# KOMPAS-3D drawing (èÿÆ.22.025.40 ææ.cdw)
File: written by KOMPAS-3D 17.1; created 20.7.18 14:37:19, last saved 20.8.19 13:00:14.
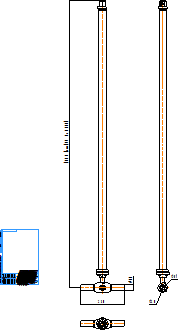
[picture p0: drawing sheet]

Sheet 1: A4, portrait

Title block, sheet 1: name: КШТ.22.025.40 С/С; sheets: 1; sheet format: A4; stored path: C:\Users\kka\KOMPAS_Work\Модели кранов для исследований\DN32\С удлинением\КШТ.22.032.40 СС.cdw

Referenced files in C:\Users\kka\KOMPAS_Work\Модели кранов для исследований\DN25\: АПТА.0203-1215.04.01 _ Корпус крана Ду25.m3d, АПТА.0203-1215.02.01 _ Патрубок сварной точенный Ду25 (труба по ГОСТ).m3d, АПТА.0203-2609.00.01 _ Шар Ду25.m3d, АПТА.0203-2609.02.03 _ Пружина тарельчатая Ду25.m3d, АПТА.0203-2609.02.04 _ Кольцо опорное Ду25.m3d, АПТА.0203-2609.02.05 _ Уплотнение седловое Ду25.m3d, АПТА.0203-2609.04.02 _ Шток Ду25 исполнение 1.m3d, АПТА.0203-1018.04.02 _ Корпус штока Ду10-32.m3d, АПТА.0203-1018.04.04 _ Шайба фрикционная Ду10-32.m3d, АПТА.0203-2609.02.02 _ Кольцо горловое Ду25.m3d, АПТА.0203-1215.00.00 _ Кран шаровой сварной Ду25 (Труба по ГОСТ).a3d!АПТА.0203-1215.00.00!Деталь (локальная).m3d, АПТА.0203-1215.00.00 _ Кран шаровой сварной Ду25 (Труба по ГОСТ).a3d!АПТА.0203-1215.00.00!Деталь (локальная) 1.m3d, Кольцо EPDM 10.3x2.4.m3d, АПТА.0203-1018.01.01 _ Кольцо прокладочное Ду10-32.m3d, Кольцо Viton 10.3x2.4.m3d, АПТА.0203-1018.01.02 _ Подкладка для кольца Ду10-32.m3d, АПТА.0203-1215.00.00 _ Кран шаровой сварной Ду25 (Труба по ГОСТ).a3d
Referenced files in C:\Program Files\ASCON\KOMPAS-3D v17\Libs\PartLib\DATA\VAULT\methods\kompas\3d\: PLib_Pin_3128_712.m3d, PLib_Blind_Nut_type1_900.m3d, PLib_Bolt_1_900.m3d, PLib_Washer_2_712.m3d, PLib_Pins_GOST_14229_911.m3d, PLib_Screw_GOST_8878-84_900.m3d
Referenced files in C:\Users\kka\KOMPAS_Work\Модели кранов для исследований\DN32\: ручка15-32.m3d, АПТА.0203-1018.03.00 _ Ручка Ду10-32.a3d
Referenced files in C:\Users\kka\KOMPAS_Work\КШ удлиненные ПП МОСФЛОУЛАЙН ф. ADL\DN25ПП\: ухватка15-32.m3d
Referenced files in C:\Users\kka\KOMPAS_Work\Удлинения БИВАЛ ф. ADL\Небюджет\Удлинения_2010\УШДн15-32\: УШ.251.00.03 _ Фланец нижний.m3d, УШ.251.00.07 _ Прокладка Ду20-50.m3d, УШ.251.00.05 _ Шток удлинителя Ду20-50.m3d, УШ.251.00.04 _ Гайка 32.m3d, УШ.251.00.01 _ Крышка удлинения.m3d, УШ.251.00.06 _ Тело удлинителя Ду20-50.m3d, УШ.251.00.08 _ Адаптер Ду20-32.m3d, УШ.251.00.00 _ Удлинение штока Ду20-32.a3d!УШ.251.00.00!Деталь (локальная).m3d, АПТА.0203-2617.11.03 - Кольцо прокладочное Ду65-80.m3d, УШ.251.00.00 _ Удлинение штока Ду20-32.a3d!УШ.251.00.00!Деталь (локальная) 1.m3d, УШ.251.00.00 _ Удлинение штока Ду20-32.a3d
Referenced files in C:\Users\kka\KOMPAS_Work\Удлинения БИВАЛ ф. ADL\Небюджет\Специальные ISO фланцы\: Фланец Ду15-32.m3d
Referenced files in C:\Users\kka\KOMPAS_Work\Модели кранов для исследований\DN80\: Кольцо EPDM 19.2x3.m3d
Referenced files in C:\Users\kka\KOMPAS_Work\Модели кранов для исследований\DN25\С удлинением\: КШТ.22.025.40 СС.a3d
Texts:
  kka
  adl
  Рама для чертежей
  Лит-Масса-Масштаб
  Материал-Предприятие
  Масштаб
  Изм.
  Лист
  № докум.
  Подп.
  Дата
  Лит.
  Разраб.
  Пров.
  Т.контр.
  Листов
  Внимание! Данный продукт является объектом авторского права ООО «Торговый Дом АДЛ».
  Запрещается изменение, копирование, распространение
  (в том числе путем копирования на другие сайты и ресурсы в Интернете)
  или любое иное использование информации и объектов без предварительного
  согласия правообладателя (ООО «Торговый Дом АДЛ»).
  Н.контр.
  Утв.
  ООО "Торговый дом АДЛ"
  Изменение
  Номер документа
  Подпись
  Обозначение документа
  Наименование изделия
  Масса изделия по ГОСТ 2.109-73
  Порядковый номер листа
  Общее количество листов в документе
  Характер работы, выполненной лицом, подписавшим документ
  Наименование или индекс предприятия, выпускающего документ
  Инв. № подл.
  Подп. и дата
  Взам. инв. №
  Инв. № дубл.
  Инвентарный номер подлинника по ГОСТ 2.501-68
  Подпись принявшего подлинник в отдел технической документации
  Инвентарный номер подлинника, взамен которого выпущен данный подлинник
  Инвентарный номер дубликата по ГОСТ 2.502-68
  Подпись принявшего дубликат в отдел технической документации
  Справ. №
  Перв. примен.
  Обозначение документа, взамен или на основании которого выпущен данный документ
  Обозначение документа, в котором впервые записан данный документ
  Подпись лица, копировавшего чертеж
  Обозначение формата листа
  !Рама для чертежа
  Корпус крана Ду25
  АПТА.0203-1215.04.01
  Патрубок сварной точенный Ду25 (труба по ГОСТ)
  АПТА.0203-1215.02.01
  Шар Ду10-15
  АПТА.0203-1018.00.01
  Пружина тарельчатая Ду25
  АПТА.0203-2609.02.03
  Кольцо опорное Ду25
  АПТА.0203-2609.02.04
  Уплотнение седловое Ду25
  АПТА.0203-2609.02.05
  Шток Ду25 исполнение 1
  АПТА.0203-2609.04.02
  Корпус штока Ду10-32
  АПТА.0203-1018.04.02
  Шайба фрикционная Ду10-32
  АПТА.0203-1018.04.04
  Кольцо горловое Ду25
  АПТА.0203-2609.02.02
  Деталь (локальная)
  Кольцо EPDM 10.3x2.4
  Кольцо прокладочное Ду10-32
  АПТА.0203-1018.01.01
  Кольцо Viton 10.3x2.4
  Подкладка для кольца Ду10-32
  АПТА.0203-1018.01.02
  Штифт 2.3x24 ГОСТ 3128-70
  ручка15-32
  ухватка15-32
  Ручка Ду10-32
  АПТА.0203-1018.03.00
  Гайка М10-6H ГОСТ 11860-85
  Кран шаровой сварной Ду25 (Труба по ГОСТ)
  АПТА.0203-1215.00.00
  Фланец нижний
  УШ.251.00.03
  Прокладка Ду20-50
  УШ.251.00.07
  Шток удлинителя Ду20-50
  УШ.251.00.05
  Гайка 32
  УШ.251.00.04
  Крышка корпуса Ду15-32
  УШ.251.00.01
  Тело удлинителя Ду20-50
  УШ.251.00.06
  Адаптер Ду20-32
  УШ.251.00.08
  Корпус
  Болт М6-6gx25 ГОСТ 7805-70
  Шайба 6 65Г 019 ГОСТ 6402-70
  Штифт A.8x12 ГОСТ 14229-93
  Штифт A.8x30 ГОСТ 14229-93
  Кольцо прокладочное Ду65-80
  АПТА.0203-2617.11.03
  Присоединительный ISO фланец Ду15-32
  ФС.1532.00.01
  Кольцо EPDM 19.2x3
  Винт М4-6gx6.14H.019 ГОСТ 8878-93
  Удлинение штока Ду20-32
  УШ.251.00.00
Dimensions and other numbers on the sheet: 1:1; 1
